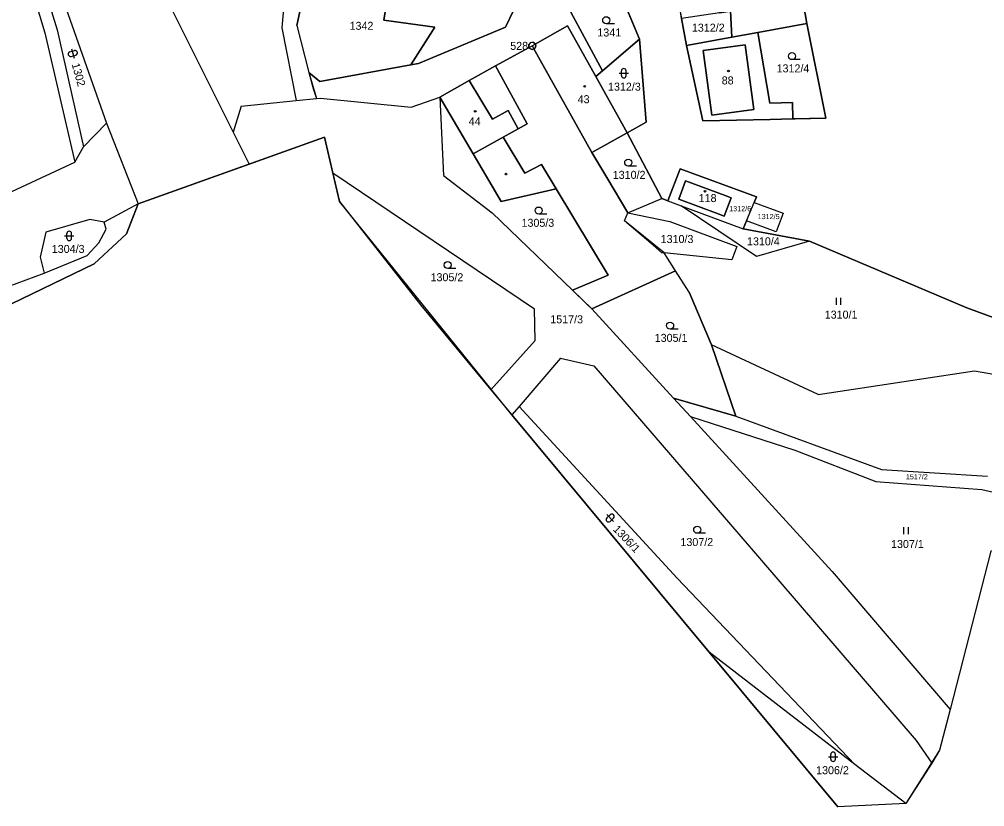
# Model space of a CAD drawing. Extents: x -760642 to -757221, y -1092371 to -1088855.
# Drawn here: x -758645.4 to -758440.5, y -1091784 to -1091616.8 of the extents above; entities that cross this region are included whole.
import ezdxf

# ---------------------------------------------------------------- set-up
doc = ezdxf.new("R2010")
doc.units = 0
for name, color, linetype in [('Vrstva 1', 7, 'Continuous'), ('Vrstva 13', 7, 'Continuous'), ('Vrstva 17', 7, 'Continuous'), ('Vrstva 18', 7, 'Continuous'), ('Vrstva 19', 7, 'Continuous'), ('Vrstva 24', 7, 'Continuous'), ('Vrstva 25', 7, 'Continuous'), ('Vrstva 26', 7, 'Continuous'), ('Vrstva 27', 7, 'Continuous'), ('Vrstva 28', 7, 'Continuous'), ('Vrstva 30', 7, 'Continuous'), ('Vrstva 4', 7, 'Continuous')]:
    doc.layers.add(name, color=color, linetype=linetype)

msp = doc.modelspace()

# ---------------------------------------------------------------- linework, layer by layer
at = {"layer": 'Vrstva 1'}
for p, q in [((-758661.45, -1091549.44), (-758639.98, -1091619.64)), ((-758639.65, -1091561.3), (-758599.98, -1091640.75)), ((-758648.7, -1091576.94), (-758626.88, -1091638.87)), ((-758647.73, -1091584.33), (-758637.41, -1091619.02)), ((-758478.2, -1091617.7), (-758481.5, -1091598.68)), ((-758588.32, -1091603.99), (-758589.69, -1091618.56)), ((-758568, -1091616.98), (-758566.09, -1091605.18)), ((-758513.74, -1091621.02), (-758519.67, -1091606.7)), ((-758586.47, -1091618.13), (-758585.31, -1091612.45)), ((-758542.23, -1091618.48), (-758540.03, -1091613.95)), ((-758528.3, -1091615.3), (-758521.6, -1091627.71)), ((-758504.8, -1091616.58), (-758503.79, -1091622.32)), ((-758494.42, -1091615.05), (-758494.14, -1091620.58)), ((-758589.69, -1091618.56), (-758586.66, -1091634.04)), ((-758586.47, -1091618.13), (-758583.92, -1091628.08)), ((-758568, -1091616.98), (-758557.18, -1091618.48)), ((-758557.18, -1091618.48), (-758562.29, -1091626.42)), ((-758542.23, -1091618.48), (-758560.7, -1091626.13)), ((-758536.52, -1091622.42), (-758529.01, -1091618.19)), ((-758529.01, -1091618.19), (-758523.04, -1091628.93)), ((-758488.64, -1091619.58), (-758478.2, -1091617.7)), ((-758474.22, -1091637.77), (-758478.2, -1091617.7)), ((-758639.98, -1091619.64), (-758633.64, -1091647.15)), ((-758637.41, -1091619.02), (-758631.82, -1091643.85)), ((-758503.79, -1091622.32), (-758494.14, -1091620.58)), ((-758494.14, -1091620.58), (-758488.64, -1091619.58)), ((-758488.64, -1091619.58), (-758486.1, -1091634.56)), ((-758544.35, -1091626.69), (-758536.52, -1091622.42)), ((-758513.74, -1091621.02), (-758521.6, -1091627.71)), ((-758513.74, -1091621.02), (-758512.31, -1091638.61)), ((-758503.79, -1091622.32), (-758500.31, -1091638.37)), ((-758562.29, -1091626.42), (-758581.64, -1091630.01)), ((-758560.7, -1091626.13), (-758562.29, -1091626.42)), ((-758549.92, -1091629.81), (-758544.35, -1091626.69)), ((-758544.35, -1091626.69), (-758537.57, -1091638.99)), ((-758581.64, -1091630.01), (-758583.92, -1091628.08)), ((-758583.92, -1091628.08), (-758583.04, -1091631.5)), ((-758521.6, -1091627.71), (-758523.04, -1091628.93)), ((-758523.04, -1091628.93), (-758516.4, -1091640.89)), ((-758556.15, -1091633.33), (-758549.92, -1091629.81)), ((-758583.04, -1091631.5), (-758582.35, -1091633.61)), ((-758598.34, -1091635.2), (-758599.98, -1091640.75)), ((-758598.34, -1091635.2), (-758586.66, -1091634.04)), ((-758586.66, -1091634.04), (-758582.35, -1091633.61)), ((-758582.35, -1091633.61), (-758581.47, -1091633.52)), ((-758581.47, -1091633.52), (-758562.24, -1091635.45)), ((-758562.24, -1091635.45), (-758556.15, -1091633.33)), ((-758549.09, -1091645.33), (-758556.15, -1091633.33)), ((-758556.15, -1091633.33), (-758555.38, -1091649.92)), ((-758486.1, -1091634.56), (-758481.27, -1091634.45)), ((-758481.27, -1091634.45), (-758481.19, -1091637.93)), ((-758631.82, -1091643.85), (-758626.88, -1091638.87)), ((-758626.88, -1091638.87), (-758620.19, -1091655.98)), ((-758539.51, -1091640.06), (-758537.57, -1091638.99)), ((-758516.4, -1091640.89), (-758512.31, -1091638.61)), ((-758500.31, -1091638.37), (-758486.02, -1091638.04)), ((-758486.02, -1091638.04), (-758481.19, -1091637.93)), ((-758481.19, -1091637.93), (-758474.22, -1091637.77)), ((-758599.98, -1091640.75), (-758596.59, -1091647.55)), ((-758542.69, -1091641.81), (-758539.51, -1091640.06)), ((-758516.4, -1091640.89), (-758523.88, -1091645.07)), ((-758516.4, -1091640.89), (-758509.01, -1091654.86)), ((-758549.09, -1091645.33), (-758542.69, -1091641.81)), ((-758633.64, -1091647.15), (-758631.82, -1091643.85)), ((-758543.13, -1091655.45), (-758549.09, -1091645.33)), ((-758523.88, -1091645.07), (-758520.71, -1091650.39)), ((-758671.11, -1091664.43), (-758633.64, -1091647.15)), ((-758536.04, -1091678.35), (-758578.85, -1091649.44)), ((-758505.13, -1091648.5), (-758507.76, -1091655.32)), ((-758488.9, -1091654.46), (-758505.13, -1091648.5)), ((-758555.38, -1091649.92), (-758545.04, -1091657.89)), ((-758520.71, -1091650.39), (-758516.26, -1091657.86)), ((-758505.41, -1091654.97), (-758503.97, -1091651.05)), ((-758503.97, -1091651.05), (-758495.55, -1091654.23)), ((-758531.44, -1091652.81), (-758543.13, -1091655.45)), ((-758531.44, -1091652.81), (-758520.39, -1091671.1)), ((-758516.26, -1091657.86), (-758509.01, -1091654.86)), ((-758507.76, -1091655.32), (-758509.01, -1091654.86)), ((-758507.76, -1091655.32), (-758504.92, -1091656.38)), ((-758497.02, -1091658.11), (-758505.41, -1091654.97)), ((-758494.31, -1091654.7), (-758495.77, -1091658.58)), ((-758495.55, -1091654.23), (-758494.31, -1091654.7)), ((-758491.01, -1091659.57), (-758489.39, -1091655.66)), ((-758489.39, -1091655.66), (-758488.9, -1091654.46)), ((-758489.39, -1091655.66), (-758483.24, -1091657.95)), ((-758620.19, -1091655.98), (-758627.39, -1091659.88)), ((-758488.89, -1091667.15), (-758504.92, -1091656.38)), ((-758504.92, -1091656.38), (-758491.72, -1091661.29)), ((-758630.42, -1091659.28), (-758639.76, -1091662)), ((-758627.39, -1091659.88), (-758630.42, -1091659.28)), ((-758545.04, -1091657.89), (-758527.98, -1091674.28)), ((-758516.94, -1091659.59), (-758516.26, -1091657.86)), ((-758510.88, -1091664.76), (-758516.94, -1091659.59)), ((-758516.26, -1091657.86), (-758507.3, -1091659.73)), ((-758507.3, -1091659.73), (-758493.12, -1091665.04)), ((-758495.77, -1091658.58), (-758497.02, -1091658.11)), ((-758491.72, -1091661.29), (-758491.01, -1091659.57)), ((-758484.72, -1091661.92), (-758491.01, -1091659.57)), ((-758483.24, -1091657.95), (-758484.72, -1091661.92)), ((-758628.55, -1091664.23), (-758627, -1091661.33)), ((-758627, -1091661.33), (-758627.39, -1091659.88)), ((-758477.68, -1091663.92), (-758491.72, -1091661.29)), ((-758639.76, -1091662), (-758641.02, -1091667.28)), ((-758631.04, -1091666.93), (-758628.55, -1091664.23)), ((-758509.03, -1091666.34), (-758510.88, -1091664.76)), ((-758493.12, -1091665.04), (-758494.17, -1091667.85)), ((-758477.68, -1091663.92), (-758488.89, -1091667.15)), ((-758444.25, -1091678.04), (-758477.68, -1091663.92)), ((-758641.02, -1091667.28), (-758640.17, -1091670.69)), ((-758640.17, -1091670.69), (-758631.04, -1091666.93)), ((-758508.55, -1091666.39), (-758509.03, -1091666.34)), ((-758494.17, -1091667.85), (-758508.55, -1091666.39)), ((-758506.12, -1091670.2), (-758508.55, -1091666.39)), ((-758649.79, -1091674.21), (-758640.17, -1091670.69)), ((-758520.39, -1091671.1), (-758527.98, -1091674.28)), ((-758523.89, -1091678.23), (-758506.12, -1091670.2)), ((-758503.23, -1091674.75), (-758506.12, -1091670.2)), ((-758527.98, -1091674.28), (-758524.99, -1091677.17)), ((-758503.23, -1091674.75), (-758498.45, -1091685.89)), ((-758524.99, -1091677.17), (-758523.89, -1091678.23)), ((-758523.89, -1091678.23), (-758506.54, -1091697.2)), ((-758417.99, -1091687.68), (-758444.25, -1091678.04)), ((-758535.91, -1091684.98), (-758536.04, -1091678.35)), ((-758535.91, -1091684.98), (-758545.28, -1091695.43)), ((-758498.45, -1091685.89), (-758493.3, -1091701.08)), ((-758475.81, -1091696.46), (-758498.45, -1091685.89)), ((-758530.5, -1091688.77), (-758539.28, -1091699)), ((-758530.5, -1091688.77), (-758523.48, -1091690.36)), ((-758523.48, -1091690.36), (-758488.27, -1091731.24)), ((-758475.81, -1091696.46), (-758442.6, -1091691.42)), ((-758442.6, -1091691.42), (-758414.22, -1091696.46)), ((-758493.3, -1091701.08), (-758506.54, -1091697.2)), ((-758506.54, -1091697.2), (-758502.96, -1091701.12)), ((-758539.28, -1091699), (-758540.82, -1091700.8)), ((-758539.28, -1091699), (-758505.76, -1091735.46)), ((-758502.96, -1091701.12), (-758472.87, -1091734.02)), ((-758502.96, -1091701.12), (-758480.75, -1091708.28)), ((-758493.3, -1091701.08), (-758462.38, -1091712.4)), ((-758480.75, -1091708.28), (-758463.57, -1091714.9)), ((-758462.38, -1091712.4), (-758439.85, -1091713.78)), ((-758463.57, -1091714.9), (-758441.09, -1091716.6)), ((-758441.09, -1091716.6), (-758407.7, -1091724.41)), ((-758488.27, -1091731.24), (-758455.02, -1091769.94)), ((-758505.76, -1091735.46), (-758468.02, -1091775)), ((-758472.87, -1091734.02), (-758447.82, -1091763.37)), ((-758468.02, -1091775), (-758498.94, -1091751.14)), ((-758455.02, -1091769.94), (-758451.71, -1091774.77)), ((-758457.23, -1091783.33), (-758468.02, -1091775))]:
    msp.add_line(p, q, dxfattribs=at)
at = {"layer": 'Vrstva 13'}
for p, q in [((-758596.59, -1091647.55), (-758580.59, -1091641.84)), ((-758580.59, -1091641.84), (-758578.85, -1091649.44)), ((-758620.19, -1091655.98), (-758596.59, -1091647.55)), ((-758578.85, -1091649.44), (-758577.47, -1091655.44)), ((-758577.47, -1091655.44), (-758560.27, -1091677.41)), ((-758622.66, -1091662.34), (-758620.19, -1091655.98)), ((-758629.54, -1091668.7), (-758622.66, -1091662.34)), ((-758647.07, -1091677.18), (-758629.54, -1091668.7)), ((-758560.27, -1091677.41), (-758545.28, -1091695.43)), ((-758545.28, -1091695.43), (-758540.82, -1091700.8)), ((-758540.82, -1091700.8), (-758498.94, -1091751.14)), ((-758439.15, -1091729.74), (-758447.82, -1091763.37)), ((-758498.94, -1091751.14), (-758471.63, -1091783.98)), ((-758447.82, -1091763.37), (-758450.05, -1091772.01)), ((-758450.05, -1091772.01), (-758451.71, -1091774.77)), ((-758451.71, -1091774.77), (-758457.23, -1091783.33)), ((-758457.23, -1091783.33), (-758471.63, -1091783.98))]:
    msp.add_line(p, q, dxfattribs=at)
at = {"layer": 'Vrstva 24'}
for radius in [0.75, 0.0327]:
    msp.add_circle((-758536.52, -1091622.42), radius, dxfattribs=at)
at = {"layer": 'Vrstva 25'}
for p, q in [((-758519.06, -1091617.73), (-758520.81, -1091617.73)), ((-758634.665, -1091623.693), (-758633.702, -1091623.421)), ((-758634.393, -1091624.655), (-758633.431, -1091624.383)), ((-758634.32, -1091623.076), (-758633.776, -1091625)), ((-758479.63, -1091625.35), (-758481.38, -1091625.35)), ((-758518.1, -1091628.23), (-758516.1, -1091628.23)), ((-758517.6, -1091628.73), (-758517.6, -1091627.73)), ((-758516.6, -1091628.73), (-758516.6, -1091627.73)), ((-758514.39, -1091647.96), (-758516.14, -1091647.96)), ((-758533.4, -1091658.14), (-758535.15, -1091658.14)), ((-758635.82, -1091662.78), (-758633.82, -1091662.78)), ((-758635.32, -1091663.28), (-758635.32, -1091662.28)), ((-758634.32, -1091663.28), (-758634.32, -1091662.28)), ((-758552.72, -1091669.7), (-758554.47, -1091669.7)), ((-758472.027, -1091675.905), (-758472.027, -1091677.405)), ((-758471.005, -1091677.405), (-758471.005, -1091675.905)), ((-758505.51, -1091682.57), (-758507.26, -1091682.57)), ((-758520.694, -1091722.663), (-758519.971, -1091721.972)), ((-758520.678, -1091721.956), (-758519.296, -1091723.402)), ((-758520.003, -1091723.386), (-758519.28, -1091722.695)), ((-758457.677, -1091724.615), (-758457.677, -1091726.115)), ((-758456.655, -1091726.115), (-758456.655, -1091724.615)), ((-758499.75, -1091725.93), (-758501.5, -1091725.93)), ((-758473.66, -1091773.38), (-758471.66, -1091773.38)), ((-758473.16, -1091773.88), (-758473.16, -1091772.88)), ((-758472.16, -1091773.88), (-758472.16, -1091772.88))]:
    msp.add_line(p, q, dxfattribs=at)
for centre, radius in [((-758520.81, -1091616.98), 0.75), ((-758481.38, -1091624.6), 0.75), ((-758494.86, -1091627.77), 0.175), ((-758525.39, -1091631.01), 0.175), ((-758548.63, -1091636.31), 0.175), ((-758516.14, -1091647.21), 0.75), ((-758542.09, -1091649.66), 0.175), ((-758499.83, -1091653.28), 0.175), ((-758535.15, -1091657.39), 0.75), ((-758554.47, -1091668.95), 0.75), ((-758507.26, -1091681.82), 0.75), ((-758501.5, -1091725.18), 0.75)]:
    msp.add_circle(centre, radius, dxfattribs=at)
for centre, start, end in [((-758634.529, -1091624.174), 105.77511, 285.77511), ((-758633.566, -1091623.902), 285.77511, 105.77511), ((-758517.1, -1091627.73), 0, 180), ((-758517.1, -1091628.73), 180, 0), ((-758634.82, -1091662.28), 0, 180), ((-758634.82, -1091663.28), 180, 0), ((-758520.348, -1091723.025), 133.68798, 313.68798), ((-758519.625, -1091722.334), 313.68798, 133.68798), ((-758472.66, -1091772.88), 0, 180), ((-758472.66, -1091773.88), 180, 0)]:
    msp.add_arc(centre, 0.5, start, end, dxfattribs=at)
at = {"layer": 'Vrstva 26'}
for points in [[(-758504.8, -1091616.58), (-758507.8, -1091596.18), (-758499.79, -1091595), (-758496.79, -1091615.4), (-758494.42, -1091615.05), (-758494.14, -1091620.58), (-758488.64, -1091619.58), (-758478.2, -1091617.7), (-758481.5, -1091598.68), (-758481.93, -1091596.22), (-758497.97, -1091594.14), (-758509.79, -1091592.61), (-758507.54, -1091603.46), (-758504.8, -1091616.58)], [(-758570.77, -1091604.28), (-758585.31, -1091612.45), (-758586.47, -1091618.13), (-758583.92, -1091628.08), (-758581.64, -1091630.01), (-758562.29, -1091626.42), (-758557.18, -1091618.48), (-758568, -1091616.98), (-758566.09, -1091605.18), (-758570.77, -1091604.28)], [(-758540.865, -1091613.822), (-758563.2, -1091610.41), (-758562.53, -1091605.86), (-758566.09, -1091605.18), (-758568, -1091616.98), (-758557.18, -1091618.48), (-758562.29, -1091626.42), (-758560.7, -1091626.13), (-758542.23, -1091618.48), (-758540.419, -1091614.75)], [(-758513.74, -1091621.02), (-758519.67, -1091606.7), (-758527.03, -1091614.04), (-758528.3, -1091615.3), (-758521.6, -1091627.71), (-758513.74, -1091621.02)], [(-758540.419, -1091614.75), (-758542.23, -1091618.48), (-758560.7, -1091626.13), (-758562.29, -1091626.42), (-758581.64, -1091630.01), (-758583.92, -1091628.08), (-758582.35, -1091633.61), (-758581.47, -1091633.52), (-758562.24, -1091635.45), (-758556.15, -1091633.33), (-758549.92, -1091629.81), (-758544.35, -1091626.69), (-758537.178, -1091622.779)], [(-758535.867, -1091622.052), (-758529.01, -1091618.19), (-758523.04, -1091628.93), (-758521.6, -1091627.71), (-758528.3, -1091615.3)], [(-758494.14, -1091620.58), (-758494.42, -1091615.05), (-758496.79, -1091615.4), (-758504.8, -1091616.58), (-758503.79, -1091622.32), (-758494.14, -1091620.58)], [(-758536.155, -1091623.075), (-758523.88, -1091645.07), (-758516.4, -1091640.89), (-758523.04, -1091628.93), (-758529.01, -1091618.19), (-758535.867, -1091622.052)], [(-758486.1, -1091634.56), (-758481.27, -1091634.45), (-758481.19, -1091637.93), (-758474.22, -1091637.77), (-758478.2, -1091617.7), (-758488.64, -1091619.58), (-758486.1, -1091634.56)], [(-758481.19, -1091637.93), (-758481.27, -1091634.45), (-758486.1, -1091634.56), (-758488.64, -1091619.58), (-758494.14, -1091620.58), (-758503.79, -1091622.32), (-758500.31, -1091638.37), (-758486.02, -1091638.04), (-758481.19, -1091637.93)], [(-758537.178, -1091622.779), (-758544.35, -1091626.69), (-758537.57, -1091638.99), (-758539.51, -1091640.06), (-758542.69, -1091641.81), (-758538.08, -1091649.47), (-758534.57, -1091647.63), (-758531.44, -1091652.81), (-758520.39, -1091671.1), (-758527.98, -1091674.28), (-758524.99, -1091677.17), (-758523.89, -1091678.23), (-758506.12, -1091670.2), (-758508.55, -1091666.39), (-758509.03, -1091666.34), (-758510.88, -1091664.76), (-758516.94, -1091659.59), (-758516.26, -1091657.86), (-758520.71, -1091650.39), (-758523.88, -1091645.07), (-758536.155, -1091623.075)], [(-758523.04, -1091628.93), (-758516.4, -1091640.89), (-758512.31, -1091638.61), (-758513.74, -1091621.02), (-758521.6, -1091627.71), (-758523.04, -1091628.93)], [(-758500.23, -1091623.4), (-758498.42, -1091637.11), (-758489.5, -1091635.93), (-758491.31, -1091622.22), (-758500.23, -1091623.4)], [(-758539.51, -1091640.06), (-758537.57, -1091638.99), (-758544.35, -1091626.69), (-758549.92, -1091629.81), (-758544.98, -1091638.01), (-758541.65, -1091636.17), (-758539.51, -1091640.06)], [(-758539.51, -1091640.06), (-758541.65, -1091636.17), (-758544.98, -1091638.01), (-758549.92, -1091629.81), (-758556.15, -1091633.33), (-758549.09, -1091645.33), (-758542.69, -1091641.81), (-758539.51, -1091640.06)], [(-758527.98, -1091674.28), (-758520.39, -1091671.1), (-758531.44, -1091652.81), (-758543.13, -1091655.45), (-758549.09, -1091645.33), (-758556.15, -1091633.33), (-758555.38, -1091649.92), (-758545.04, -1091657.89), (-758527.98, -1091674.28)], [(-758523.88, -1091645.07), (-758520.71, -1091650.39), (-758516.26, -1091657.86), (-758509.01, -1091654.86), (-758516.4, -1091640.89), (-758523.88, -1091645.07)], [(-758534.57, -1091647.63), (-758538.08, -1091649.47), (-758542.69, -1091641.81), (-758549.09, -1091645.33), (-758543.13, -1091655.45), (-758531.44, -1091652.81), (-758534.57, -1091647.63)], [(-758504.92, -1091656.38), (-758491.72, -1091661.29), (-758491.01, -1091659.57), (-758489.39, -1091655.66), (-758488.9, -1091654.46), (-758505.13, -1091648.5), (-758507.76, -1091655.32), (-758504.92, -1091656.38)], [(-758505.41, -1091654.97), (-758497.02, -1091658.11), (-758495.77, -1091658.58), (-758494.31, -1091654.7), (-758495.55, -1091654.23), (-758503.97, -1091651.05), (-758505.41, -1091654.97)], [(-758506.54, -1091697.2), (-758493.3, -1091701.08), (-758498.45, -1091685.89), (-758503.23, -1091674.75), (-758506.12, -1091670.2), (-758523.89, -1091678.23), (-758506.54, -1091697.2)]]:
    msp.add_lwpolyline(points, dxfattribs=at)
for start, end in [(29.39034, 180), (180, 208.60533), (208.60533, 299.16402), (299.16402, 0), (0, 29.39034)]:
    msp.add_arc((-758536.52, -1091622.42), 0.75, start, end, dxfattribs=at)
at = {"layer": 'Vrstva 27'}
for points in [[(-758504.8, -1091616.58), (-758503.79, -1091622.32), (-758500.31, -1091638.37), (-758474.22, -1091637.77), (-758478.2, -1091617.7), (-758481.5, -1091598.68)], [(-758583.65, -1091604.35), (-758586.47, -1091618.13), (-758583.92, -1091628.08), (-758582.35, -1091633.61), (-758581.47, -1091633.52), (-758562.24, -1091635.45), (-758556.15, -1091633.33), (-758555.38, -1091649.92), (-758545.04, -1091657.89), (-758527.98, -1091674.28), (-758523.89, -1091678.23), (-758506.54, -1091697.2), (-758493.3, -1091701.08), (-758498.45, -1091685.89), (-758503.23, -1091674.75), (-758506.12, -1091670.2), (-758508.55, -1091666.39), (-758516.94, -1091659.59), (-758516.26, -1091657.86), (-758509.01, -1091654.86), (-758507.76, -1091655.32), (-758504.92, -1091656.38), (-758491.72, -1091661.29), (-758488.9, -1091654.46), (-758505.13, -1091648.5), (-758507.76, -1091655.32), (-758509.01, -1091654.86), (-758516.4, -1091640.89), (-758512.31, -1091638.61), (-758513.74, -1091621.02), (-758519.67, -1091606.7)]]:
    msp.add_lwpolyline(points, dxfattribs=at)
at = {"layer": 'Vrstva 28'}
msp.add_lwpolyline([(-758191.83, -1091739.12), (-758210.04, -1091740.53), (-758230.21, -1091739.12), (-758246.53, -1091736.12), (-758264.13, -1091731.78), (-758283.06, -1091731.52), (-758333.68, -1091727.28), (-758402.14, -1091723.47), (-758439.15, -1091729.74), (-758447.82, -1091763.37), (-758450.05, -1091772.01), (-758457.23, -1091783.33), (-758471.63, -1091783.98), (-758498.94, -1091751.14), (-758540.82, -1091700.8), (-758577.47, -1091655.44), (-758580.59, -1091641.84), (-758620.19, -1091655.98), (-758622.66, -1091662.34), (-758629.54, -1091668.7), (-758647.07, -1091677.18)], dxfattribs=at)
at = {"layer": 'Vrstva 30'}
for points in [[(-758481.5, -1091598.68), (-758478.2, -1091617.7), (-758474.22, -1091637.77), (-758481.19, -1091637.93)], [(-758519.67, -1091606.7), (-758513.74, -1091621.02), (-758512.31, -1091638.61), (-758516.4, -1091640.89), (-758509.01, -1091654.86), (-758507.76, -1091655.32), (-758505.13, -1091648.5), (-758488.9, -1091654.46), (-758489.39, -1091655.66), (-758483.24, -1091657.95), (-758484.72, -1091661.92), (-758491.01, -1091659.57), (-758491.72, -1091661.29), (-758477.68, -1091663.92), (-758444.25, -1091678.04), (-758417.99, -1091687.68)], [(-758481.19, -1091637.93), (-758486.02, -1091638.041), (-758500.31, -1091638.37), (-758503.79, -1091622.32), (-758504.8, -1091616.58)]]:
    msp.add_lwpolyline(points, dxfattribs=at)
at = {"layer": 'Vrstva 4'}
for p, q in [((-758536.52, -1091622.42), (-758523.88, -1091645.07)), ((-758500.23, -1091623.4), (-758491.31, -1091622.22)), ((-758491.31, -1091622.22), (-758489.5, -1091635.93)), ((-758498.42, -1091637.11), (-758500.23, -1091623.4)), ((-758544.98, -1091638.01), (-758549.92, -1091629.81)), ((-758544.98, -1091638.01), (-758541.65, -1091636.17)), ((-758541.65, -1091636.17), (-758539.51, -1091640.06)), ((-758489.5, -1091635.93), (-758498.42, -1091637.11)), ((-758542.69, -1091641.81), (-758538.08, -1091649.47)), ((-758538.08, -1091649.47), (-758534.57, -1091647.63)), ((-758531.44, -1091652.81), (-758534.57, -1091647.63))]:
    msp.add_line(p, q, dxfattribs=at)

# ---------------------------------------------------------------- texts
at = {"layer": 'Vrstva 17'}
msp.add_text('528', height=1.7, dxfattribs=at).set_placement((-758541.196, -1091623.27))
at = {"layer": 'Vrstva 18'}
for s, height, p in [('1342', 1.7, (-758575.3, -1091619.01)), ('1341', 1.7, (-758522.7, -1091620.43)), ('1312/2', 1.7, (-758502.63, -1091619.41)), ('1312/4', 1.7, (-758484.645, -1091628.05)), ('1312/3', 1.7, (-758520.44, -1091631.93)), ('1310/2', 1.7, (-758519.43, -1091650.66)), ('1312/6', 1.1, (-758494.7, -1091657.53)), ('1305/3', 1.7, (-758538.8, -1091660.84)), ('1312/5', 1.1, (-758488.656, -1091659.21)), ('1310/3', 1.7, (-758509.26, -1091664.29)), ('1310/4', 1.7, (-758490.93, -1091664.78)), ('1304/3', 1.7, (-758638.518, -1091666.39)), ('1305/2', 1.7, (-758558.107, -1091672.4)), ('1517/3', 1.7, (-758532.696, -1091681.34)), ('1310/1', 1.7, (-758474.43, -1091680.34)), ('1305/1', 1.7, (-758510.52, -1091685.27)), ('1517/2', 1.1, (-758457.198, -1091714.47)), ('1307/2', 1.7, (-758505.06, -1091728.63)), ('1307/1', 1.7, (-758460.348, -1091729.05)), ('1306/2', 1.7, (-758476.256, -1091777.08))]:
    msp.add_text(s, height=height, dxfattribs=at).set_placement(p)
for s, rotation, p in [('1302', 285.7752, (-758634.325, -1091626.322)), ('1306/1', 313.68807, (-758519.488, -1091725.181))]:
    msp.add_text(s, height=1.7, rotation=rotation, dxfattribs=at).set_placement(p)
at = {"layer": 'Vrstva 19'}
for s, p in [('88', (-758496.297, -1091630.61)), ('43', (-758526.88, -1091634.6)), ('44', (-758550, -1091639.27)), ('118', (-758501.19, -1091655.59))]:
    msp.add_text(s, height=1.7, dxfattribs=at).set_placement(p)

doc.saveas('drawing.dxf')
